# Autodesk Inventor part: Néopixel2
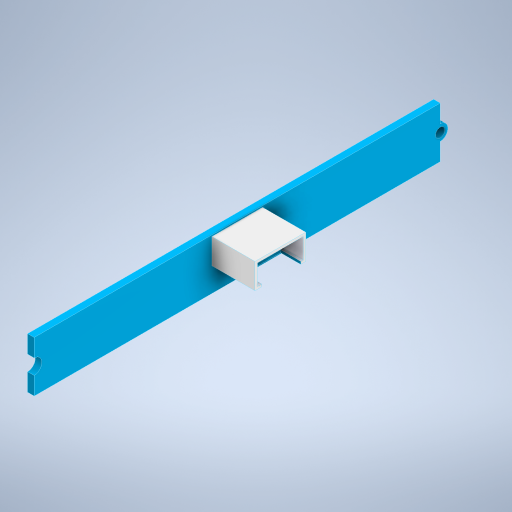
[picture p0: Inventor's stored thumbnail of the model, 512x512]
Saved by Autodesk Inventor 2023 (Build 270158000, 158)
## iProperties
Created: 2022-12
Part Number: Néopixel2
Material: Générique
Document SubType Name: Modeling
Designer: ecuenot
Density: 1 g/cm^3
Appearance: Bleu ciel moyen
Author: ecuenot
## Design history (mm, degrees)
sketch "Esquisse1"
  geometry: L1 (10, 59.976)-(10, -20.024); L2 (0, -20.024)-(0, 0); L3 (0, 0)-(8, 0); L4 (10, -20.024)-(8, -20.024); L5 (0, 59.976)-(0, 59.976); L6 (0, 59.976)-(0, 0); L7 (8, -20.024)-(5.884, -20.024); L8 (4.021, -20.024)-(0, -20.024); L9 (0, 59.976)-(3.5, 59.976); L10 (6.5, 59.976)-(10, 59.976); A1 r 3.048 centre (4.952, -20.024) between (8, -20.024) and (8, -20.024); A2 r 1.5 centre (4.952, -20.024) between (3.452, -20.024) and (6.452, -20.024); A3 r 0.931 centre (4.952, -20.024) between (5.884, -20.024) and (4.021, -20.024); A4 r 1.5 centre (5, 59.976) between (3.5, 59.976) and (6.5, 59.976); 2 further points
  constraints: 20 end point, 10 parallel, 8 point on circle, 4 centre point, 4 horizontal, 3 perpendicular, 2 coincident, 2 point on line, 1 collinear
  dimensions: "d0" = 10 distance of L1.end L2.start; "d1" = 80 distance of L1.start L1.end; "d47" = 3 diameter of A4; "d48" = 5 distance from line of L1 A4.centre
extrude "Extrusion1" new body sketch "Esquisse1" distance "d9" = 1.3; taper "d10" = 0 deg
sketch "Esquisse6"
  geometry: L1 (20.024, 10)-(-59.976, 10) reference; L2 (-14.976, 4.72)-(-24.976, 4.72); L3 (-24.976, 4.72)-(-24.976, 9.72); L4 (-24.976, 9.72)-(-14.976, 9.72); L5 (-14.976, 9.72)-(-14.976, 4.72); L6 (-14.976, 4.72)-(-24.976, 9.72); L7 (-24.976, 4.72)-(-14.976, 9.72); L8 (-19.976, 10)-(-19.976, 24.898); L9 (-19.976, 7.22)-(-19.976, 10); 2 further points
  constraints: 16 end point, 3 midpoint, 2 parallel, 2 perpendicular, 1 horizontal, 1 vertical
  dimensions: "d36" = 10 distance of L3.end L4.end; "d37" = 5 distance of L2.end L3.end
extrude "Extrusion4" join sketch "Esquisse6" distance "d38" = 8.5; taper "d39" = 0 deg
feature "Coque2" dims "d41" = 0.5
sketch "Esquisse8"
  geometry: L1 (9.196, 0.99)-(4.537, 0.99); L2 (4.537, 0.99)-(4.537, 8.686); L3 (4.537, 8.686)-(9.196, 8.686); L4 (9.196, 8.686)-(9.196, 0.99); 1 further point
  constraints: 8 end point, 2 parallel, 1 horizontal, 1 perpendicular
extrude "Extrusion6" cut sketch "Esquisse8" distance "d49" = 1.3; taper "d50" = 0 deg
sketch "Esquisse9"
  geometry: L1 (-16.024, 6.652)-(-12.624, 6.652); L2 (-12.624, 6.652)-(-12.624, 3.252); L3 (-12.624, 3.252)-(-16.024, 3.252); L4 (-16.024, 3.252)-(-16.024, 6.652); L5 (-20.024, 4.952)-(-4.192, 4.952); L6 (-20.024, 6.452)-(-20.024, 10) reference; C1 r 0.931 at (-20.024, 4.952) reference; 2 further points
  constraints: 10 end point, 2 horizontal, 2 parallel, 1 midpoint, 1 perpendicular, 1 point on line
  dimensions: "d51" = 3.4 distance of L2.end L3.end; "d52" = 3.4 distance of L1.end L2.end; "d53" = 4 distance between parallel lines of L4 L6
extrude "Extrusion7" join sketch "Esquisse9" distance "d54" = 1.3; taper "d55" = 0 deg
sketch "Esquisse10"
  geometry: L1 (-15.116, 6.246)-(-13.547, 6.246); L2 (-13.047, 5.746)-(-13.047, 4.301); L3 (-13.547, 3.801)-(-15.116, 3.801); L4 (-15.616, 4.301)-(-15.616, 5.746); A1 r 0.5 centre (-13.547, 5.746) between (-13.047, 5.746) and (-13.547, 6.246); A2 r 0.5 centre (-15.116, 5.746) between (-15.116, 6.246) and (-15.616, 5.746); A3 r 0.5 centre (-15.116, 4.301) between (-15.616, 4.301) and (-15.116, 3.801); A4 r 0.5 centre (-13.547, 4.301) between (-13.547, 3.801) and (-13.047, 4.301); 1 further point
  constraints: 8 end point, 8 point on circle, 8 tangent, 4 centre point, 3 equal radius, 2 parallel, 1 horizontal, 1 perpendicular
  dimensions: "d56" = 0.5 radius of A1
extrude "Extrusion8" cut sketch "Esquisse10" distance "d57" = 0.2; taper "d58" = 0 deg
pattern_linear "Réseau rectangulaire1" dims "d61" = 7.5
node "Solide1"
